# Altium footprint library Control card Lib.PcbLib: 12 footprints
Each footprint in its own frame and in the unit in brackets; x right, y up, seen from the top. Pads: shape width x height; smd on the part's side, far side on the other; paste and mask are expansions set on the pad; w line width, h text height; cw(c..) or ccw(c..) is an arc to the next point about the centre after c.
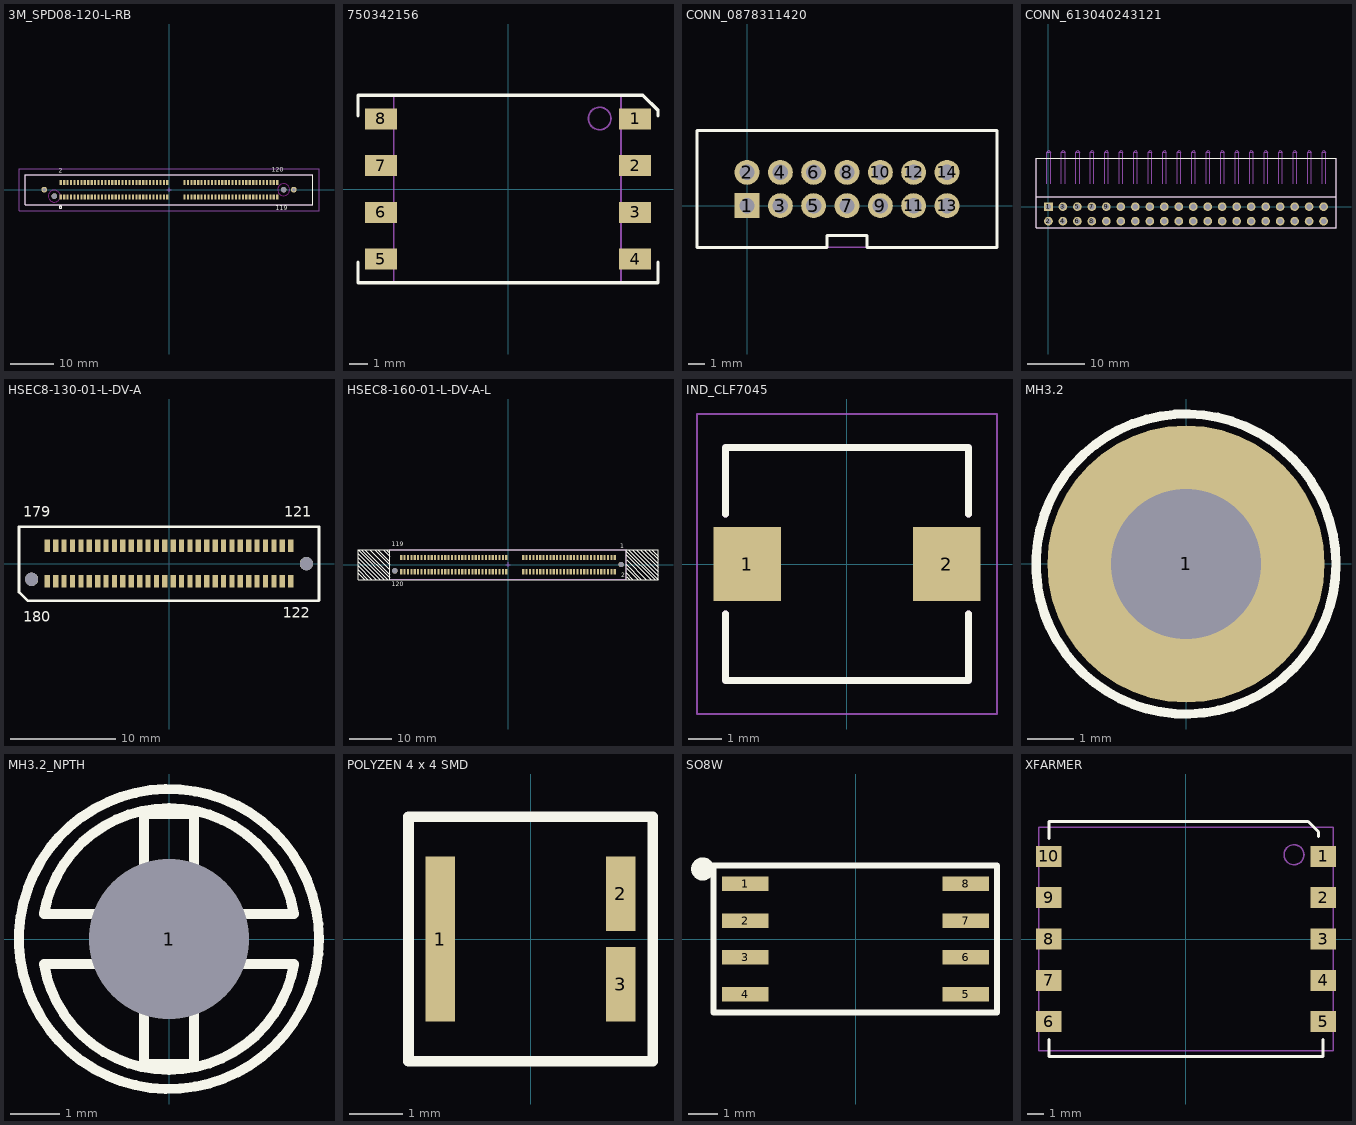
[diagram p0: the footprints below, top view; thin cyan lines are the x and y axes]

## 3M_SPD08-120-L-RB [mm] "CONN HIGH SPD CARD EDGE 120 POS"
height 12.4
pads (124):
  rect 0.5x1.2 smd mask+0: 1(-25.2,-1.7) 2(-25.2,1.7) 3(-24.4,-1.7) 4(-24.4,1.7) 5(-23.6,-1.7) 6(-23.6,1.7) 7(-22.8,-1.7) 8(-22.8,1.7) 9(-22,-1.7) 10(-22,1.7) 11(-21.2,-1.7) 12(-21.2,1.7) 13(-20.4,-1.7) 14(-20.4,1.7) 15(-19.6,-1.7) 16(-19.6,1.7) 17(-18.8,-1.7) 18(-18.8,1.7) 19(-18,-1.7) 20(-18,1.7) 21(-17.2,-1.7) 22(-17.2,1.7) 23(-16.4,-1.7) 24(-16.4,1.7) 25(-15.6,-1.7) 26(-15.6,1.7) 27(-14.8,-1.7) 28(-14.8,1.7) 29(-14,-1.7) 30(-14,1.7) 31(-13.2,-1.7) 32(-13.2,1.7) 33(-12.4,-1.7) 34(-12.4,1.7) 35(-11.6,-1.7) 36(-11.6,1.7) 37(-10.8,-1.7) 38(-10.8,1.7) 39(-10,-1.7) 40(-10,1.7) 41(-9.2,-1.7) 42(-9.2,1.7) 43(-8.4,-1.7) 44(-8.4,1.7) 45(-7.6,-1.7) 46(-7.6,1.7) 47(-6.8,-1.7) 48(-6.8,1.7) 49(-6,-1.7) 50(-6,1.7) 51(-5.2,-1.7) 52(-5.2,1.7) 53(-4.4,-1.7) 54(-4.4,1.7) 55(-3.6,-1.7) 56(-3.6,1.7) 57(-2.8,-1.7) 58(-2.8,1.7) 59(-2,-1.7) 60(-2,1.7) 61(-1.2,-1.7) 62(-1.2,1.7) 63(-0.4,-1.7) 64(-0.4,1.7) 65(3.6,-1.7) 66(3.6,1.7) 67(4.4,-1.7) 68(4.4,1.7) 69(5.2,-1.7) 70(5.2,1.7) 71(6,-1.7) 72(6,1.7) 73(6.8,-1.7) 74(6.8,1.7) 75(7.6,-1.7) 76(7.6,1.7) 77(8.4,-1.7) 78(8.4,1.7) 79(9.2,-1.7) 80(9.2,1.7) 81(10,-1.7) 82(10,1.7) 83(10.8,-1.7) 84(10.8,1.7) 85(11.6,-1.7) 86(11.6,1.7) 87(12.4,-1.7) 88(12.4,1.7) 89(13.2,-1.7) 90(13.2,1.7) 91(14,-1.7) 92(14,1.7) 93(14.8,-1.7) 94(14.8,1.7) 95(15.6,-1.7) 96(15.6,1.7) 97(16.4,-1.7) 98(16.4,1.7) 99(17.2,-1.7) 100(17.2,1.7) 101(18,-1.7) 102(18,1.7) 103(18.8,-1.7) 104(18.8,1.7) 105(19.6,-1.7) 106(19.6,1.7) 107(20.4,-1.7) 108(20.4,1.7) 109(21.2,-1.7) 110(21.2,1.7) 111(22,-1.7) 112(22,1.7) 113(22.8,-1.7) 114(22.8,1.7) 115(23.6,-1.7) 116(23.6,1.7) 117(24.4,-1.7) 118(24.4,1.7) 119(25.2,-1.7) 120(25.2,1.7)
  round 1.27 hole 1.27 unplated mask+0: 121(-26.7,-1.5) 122(26.7,0)
  round 1.34 hole 0.84 mask+0: 123(-29.05,0) 124(29.05,0)
Top Overlay:
  circle w0.152: c-25.279,-4.1 r0.279
  lines w0.152: 27.9,-3.556 27.9,-3.556 ; 27.9,3.5 27.9,3.5
  lines w0.178: -33.525,-3.5 -33.525,3.5 33.525,3.5 33.525,-3.5 -33.525,-3.5
  text "119" at 24.9,-4.8 h1.02
  text "2" at -25.7,3.9 h1.02
  text "120" at 23.9,4.2 h1.02
Keep-Out Layer:
  circle w0.152: c26.7,0 r1.397
  circle w0.152: c-26.7,-1.5 r1.397
Mechanical 5:
  lines w0.127: -33.525,-3.5 -33.525,3.5 33.525,3.5 33.525,-3.5 -33.525,-3.5
Mechanical 9:
  circle w0.025: c-25.279,-4.1 r0.279
  text ".Designator" at -6.096,-0.508 h1.27
Mechanical 15:
  lines w0.1: -0.5,0 0.5,0 ; 0,-0.5 0,0.5
  lines w0.127: -34.922,-4.897 -34.922,4.897 34.922,4.897 34.922,-4.897 -34.922,-4.897

## 750342156 [mm]
height 11.5
pads (8):
  rect 1.7x1.12 smd: 1(6.78,3.735) 2(6.78,1.245) 3(6.78,-1.245) 4(6.78,-3.735) 5(-6.78,-3.735) 6(-6.78,-1.245) 7(-6.78,1.245) 8(-6.78,3.735)
Top Overlay:
  lines w0.18: -8.001,-3.9 -8.001,-5 8.001,-5 8.001,-3.9 ; -8.001,3.9 -8.001,5 7.192,5 8.001,4.191 8.001,3.9
Mechanical 5:
  circle w0.1: c4.886,3.759 r0.6
  lines w0.1: -6.096,-5 6.035,-5 6.035,5 -6.096,5 -6.096,-5
  text ".Designator" at -2,-0.5 h1.02
3D body: height 5.97, standoff 0, extent -6.034,-4.999 6.034,4.999
3D body: height 5.98, standoff 5, extent 4.266,3.123 5.488,4.345

## CONN_0878311420 [mm]
height 6.35
pads (14):
  rect 1.5x1.5 hole 0.914: 1(0,0)
  round 1.5 hole 0.914: 2(0,2) 3(2,0) 4(2,2) 5(4,0) 6(4,2) 7(6,0) 8(6,2) 9(8,0) 10(8,2) 11(10,0) 12(10,2) 13(12,0) 14(12,2)
Top Overlay:
  lines w0.178: -3,-2.5 -3,4.5 15,4.5 15,-2.5 10.5,-2.5 7.2,-2.5 7.2,-1.8 4.8,-1.8 4.8,-2.5 -3,-2.5
Mechanical 5:
  lines w0.1: -3,-2.5 -3,4.5 15,4.5 15,-2.5 -3,-2.5
  text ".Designator" at 1.1,0.7 h1.02

## CONN_613040243121 [mil]
pads (40):
  rect 60x60 hole 38: 1(0,0)
  round 60 hole 38: 2(0,-100) 3(100,0) 4(100,-100) 5(200,0) 6(200,-100) 7(300,0) 8(300,-100) 9(400,0) 10(400,-100) 11(500,0) 12(500,-100) 13(600,0) 14(600,-100) 15(700,0) 16(700,-100) 17(800,0) 18(800,-100) 19(900,0) 20(900,-100) 21(1000,0) 22(1000,-100) 23(1100,0) 24(1100,-100) 25(1200,0) 26(1200,-100) 27(1300,0) 28(1300,-100) 29(1400,0) 30(1400,-100) 31(1500,0) 32(1500,-100) 33(1600,0) 34(1600,-100) 35(1700,0) 36(1700,-100) 37(1800,0) 38(1800,-100) 39(1900,0) 40(1900,-100)
Top Overlay:
  lines w5: -86,70 1986,70 ; -85,-145.5 -85,335 1986,335 1986,-145.5 -85,-145.5
Mechanical 5:
  lines w5: -86,70 1986,70 ; -85,-145.5 1986,-145.5 1986,335 -85,335 -85,-145.5
  text ".Designator" at 877,-70 h40
Mechanical 17:
  lines w1: -10.5,160 -10.5,377.5 ; 14.5,160 14.5,377.5 ; 89.5,160 89.5,377.5 ; 114.5,160 114.5,377.5 ; 189.5,160 189.5,377.5 ; 214.5,160 214.5,377.5 ; 289.5,160 289.5,377.5 ; 314.5,160 314.5,377.5 ; 389.5,160 389.5,377.5 ; 414.5,160 414.5,377.5 ; 489.5,160 489.5,377.5 ; 514.5,160 514.5,377.5 ; 589.5,160 589.5,377.5 ; 614.5,160 614.5,377.5 ; 689.5,160 689.5,377.5 ; 714.5,160 714.5,377.5 ; 789.5,160 789.5,377.5 ; 814.5,160 814.5,377.5 ; 889.5,160 889.5,377.5 ; 914.5,160 914.5,377.5 ; 989.5,160 989.5,377.5 ; 1014.5,160 1014.5,377.5 ; 1089.5,160 1089.5,377.5 ; 1114.5,160 1114.5,377.5 ; 1189.5,160 1189.5,377.5 ; 1214.5,160 1214.5,377.5 ; 1289.5,160 1289.5,377.5 ; 1314.5,160 1314.5,377.5 ; 1389.5,160 1389.5,377.5 ; 1414.5,160 1414.5,377.5 ; 1489.5,160 1489.5,377.5 ; 1514.5,160 1514.5,377.5 ; 1589.5,160 1589.5,377.5 ; 1614.5,160 1614.5,377.5 ; 1689.5,160 1689.5,377.5 ; 1714.5,160 1714.5,377.5 ; 1789.5,160 1789.5,377.5 ; 1814.5,160 1814.5,377.5 ; 1889.5,160 1889.5,377.5 ; 1914.5,160 1914.5,377.5 ; -10.5,377.5 2,390 14.5,377.5 ; -10.5,377.5 14.5,377.5 ; 89.5,377.5 114.5,377.5 ; 89.5,377.5 102,390 114.5,377.5 ; 189.5,377.5 202,390 214.5,377.5 ; 189.5,377.5 214.5,377.5 ; 289.5,377.5 302,390 314.5,377.5 ; 289.5,377.5 314.5,377.5 ; 389.5,377.5 402,390 414.5,377.5 ; 389.5,377.5 414.5,377.5 ; 489.5,377.5 514.5,377.5 ; 489.5,377.5 502,390 514.5,377.5 ; 589.5,377.5 602,390 614.5,377.5 ; 589.5,377.5 614.5,377.5 ; 689.5,377.5 702,390 714.5,377.5 ; 689.5,377.5 714.5,377.5 ; 789.5,377.5 802,390 814.5,377.5 ; 789.5,377.5 814.5,377.5 ; 889.5,377.5 902,390 914.5,377.5 ; 889.5,377.5 914.5,377.5 ; 989.5,377.5 1014.5,377.5 ; 989.5,377.5 1002,390 1014.5,377.5 ; 1089.5,377.5 1114.5,377.5 ; 1089.5,377.5 1102,390 1114.5,377.5 ; 1189.5,377.5 1214.5,377.5 ; 1189.5,377.5 1202,390 1214.5,377.5 ; 1289.5,377.5 1302,390 1314.5,377.5 ; 1289.5,377.5 1314.5,377.5 ; 1389.5,377.5 1402,390 1414.5,377.5 ; 1389.5,377.5 1414.5,377.5 ; 1489.5,377.5 1502,390 1514.5,377.5 ; 1489.5,377.5 1514.5,377.5 ; 1589.5,377.5 1602,390 1614.5,377.5 ; 1589.5,377.5 1614.5,377.5 ; 1689.5,377.5 1702,390 1714.5,377.5 ; 1689.5,377.5 1714.5,377.5 ; 1789.5,377.5 1802,390 1814.5,377.5 ; 1789.5,377.5 1814.5,377.5 ; 1889.5,377.5 1902,390 1914.5,377.5 ; 1889.5,377.5 1914.5,377.5

## HSEC8-130-01-L-DV-A [mm]
pads (62):
  rect 0.5x1.2 smd: 121(11.6,1.7) 122(11.6,-1.7) 123(10.8,1.7) 124(10.8,-1.7) 125(10,1.7) 126(10,-1.7) 127(9.2,1.7) 128(9.2,-1.7) 129(8.4,1.7) 130(8.4,-1.7) 131(7.6,1.7) 132(7.6,-1.7) 133(6.8,1.7) 134(6.8,-1.7) 135(6,1.7) 136(6,-1.7) 137(5.2,1.7) 138(5.2,-1.7) 139(4.4,1.7) 140(4.4,-1.7) 141(3.6,1.7) 142(3.6,-1.7) 143(2.8,1.7) 144(2.8,-1.7) 145(2,1.7) 146(2,-1.7) 147(1.2,1.7) 148(1.2,-1.7) 149(0.4,1.7) 150(0.4,-1.7) 151(-0.4,1.7) 152(-0.4,-1.7) 153(-1.2,1.7) 154(-1.2,-1.7) 155(-2,1.7) 156(-2,-1.7) 157(-2.8,1.7) 158(-2.8,-1.7) 159(-3.6,1.7) 160(-3.6,-1.7) 161(-4.4,1.7) 162(-4.4,-1.7) 163(-5.2,1.7) 164(-5.2,-1.7) 165(-6,1.7) 166(-6,-1.7) 167(-6.8,1.7) 168(-6.8,-1.7) 169(-7.6,1.7) 170(-7.6,-1.7) 171(-8.4,1.7) 172(-8.4,-1.7) 173(-9.2,1.7) 174(-9.2,-1.7) 175(-10,1.7) 176(-10,-1.7) 177(-10.8,1.7) 178(-10.8,-1.7) 179(-11.6,1.7) 180(-11.6,-1.7)
  round 1.27 hole 1.27 unplated mask+0: 181(13.1,0) 182(-13.1,-1.5)
Top Overlay:
  lines w0.254: 14.246,-3.554 -13.464,-3.554 -14.3,-2.718 -14.3,1.75 -14.3,3.5 14.3,3.5 14.3,-3.5
  text "180" at -13.898,-5.563 h1.02
  text "179" at -13.898,4.47 h1.02
  text "121" at 10.994,4.47 h1.02
  text "122" at 10.867,-5.182 h1.02
Mechanical 13:
  lines w0.1: -14.3,-2.7 -14.3,3.5 14.3,3.5 14.3,-3.5 -13.5,-3.5 -14.3,-2.7

## HSEC8-160-01-L-DV-A-L [mm]
pads (122):
  rect 0.5x1.2 smd: 1(25.2,1.7) 2(25.2,-1.7) 3(24.4,1.7) 4(24.4,-1.7) 5(23.6,1.7) 6(23.6,-1.7) 7(22.8,1.7) 8(22.8,-1.7) 9(22,1.7) 10(22,-1.7) 11(21.2,1.7) 12(21.2,-1.7) 13(20.4,1.7) 14(20.4,-1.7) 15(19.6,1.7) 16(19.6,-1.7) 17(18.8,1.7) 18(18.8,-1.7) 19(18,1.7) 20(18,-1.7) 21(17.2,1.7) 22(17.2,-1.7) 23(16.4,1.7) 24(16.4,-1.7) 25(15.6,1.7) 26(15.6,-1.7) 27(14.8,1.7) 28(14.8,-1.7) 29(14,1.7) 30(14,-1.7) 31(13.2,1.7) 32(13.2,-1.7) 33(12.4,1.7) 34(12.4,-1.7) 35(11.6,1.7) 36(11.6,-1.7) 37(10.8,1.7) 38(10.8,-1.7) 39(10,1.7) 40(10,-1.7) 41(9.2,1.7) 42(9.2,-1.7) 43(8.4,1.7) 44(8.4,-1.7) 45(7.6,1.7) 46(7.6,-1.7) 47(6.8,1.7) 48(6.8,-1.7) 49(6,1.7) 50(6,-1.7) 51(5.2,1.7) 52(5.2,-1.7) 53(4.4,1.7) 54(4.4,-1.7) 55(3.6,1.7) 56(3.6,-1.7) 57(-0.4,1.7) 58(-0.4,-1.7) 59(-1.2,1.7) 60(-1.2,-1.7) 61(-2,1.7) 62(-2,-1.7) 63(-2.8,1.7) 64(-2.8,-1.7) 65(-3.6,1.7) 66(-3.6,-1.7) 67(-4.4,1.7) 68(-4.4,-1.7) 69(-5.2,1.7) 70(-5.2,-1.7) 71(-6,1.7) 72(-6,-1.7) 73(-6.8,1.7) 74(-6.8,-1.7) 75(-7.6,1.7) 76(-7.6,-1.7) 77(-8.4,1.7) 78(-8.4,-1.7) 79(-9.2,1.7) 80(-9.2,-1.7) 81(-10,1.7) 82(-10,-1.7) 83(-10.8,1.7) 84(-10.8,-1.7) 85(-11.6,1.7) 86(-11.6,-1.7) 87(-12.4,1.7) 88(-12.4,-1.7) 89(-13.2,1.7) 90(-13.2,-1.7) 91(-14,1.7) 92(-14,-1.7) 93(-14.8,1.7) 94(-14.8,-1.7) 95(-15.6,1.7) 96(-15.6,-1.7) 97(-16.4,1.7) 98(-16.4,-1.7) 99(-17.2,1.7) 100(-17.2,-1.7) 101(-18,1.7) 102(-18,-1.7) 103(-18.8,1.7) 104(-18.8,-1.7) 105(-19.6,1.7) 106(-19.6,-1.7) 107(-20.4,1.7) 108(-20.4,-1.7) 109(-21.2,1.7) 110(-21.2,-1.7) 111(-22,1.7) 112(-22,-1.7) 113(-22.8,1.7) 114(-22.8,-1.7) 115(-23.6,1.7) 116(-23.6,-1.7) 117(-24.4,1.7) 118(-24.4,-1.7) 119(-25.2,1.7) 120(-25.2,-1.7)
  round 1.27 hole 1.27 unplated mask+0: 121(-26.7,-1.5) 122(26.7,0)
Top Overlay:
  lines w0.2: -35.4,-2.032 -33.909,-3.523 ; -35.4,-1.27 -33.114,-3.556 ; -35.4,0.635 -31.242,-3.523 ; -35.4,1.651 -30.226,-3.523 ; -35.4,2.54 -29.337,-3.523 ; -35.353,-0.334 -32.131,-3.556 ; -34.58,3.465 -27.94,-3.175 ; -33.782,3.5 -27.9,-2.382 ; -32.639,3.5 -27.996,-1.143 ; -31.496,3.5 -27.9,-0.096 ; -30.734,3.5 -27.996,0.762 ; -29.464,3.5 -27.9,1.936 ; -28.702,3.5 -27.996,2.794 ; -28.344,-3.556 -35.4,3.5 ; 27.9,-1.992 29.464,-3.556 ; 27.9,0.04 31.496,-3.556 ; 27.9,2.326 33.782,-3.556 ; 27.94,3.119 34.58,-3.52 ; 27.996,-2.85 28.702,-3.556 ; 27.996,-0.818 30.734,-3.556 ; 27.996,1.087 32.639,-3.556 ; 28.344,3.5 35.4,-3.556 ; 29.337,3.467 35.4,-2.596 ; 30.226,3.467 35.4,-1.707 ; 31.242,3.467 35.4,-0.691 ; 32.131,3.5 35.353,0.278 ; 33.114,3.5 35.4,1.214 ; 33.909,3.467 35.4,1.976 ; -35.4,3.5 -27.9,3.5 ; -35.4,3.5 -35.4,-3.556 -27.9,-3.556 ; -27.9,-3.556 -27.9,3.5 ; -27.9,-3.556 27.9,-3.556 ; -27.9,3.5 27.9,3.5 ; 27.9,-3.556 27.9,3.5 ; 27.9,-3.556 35.4,-3.556 ; 27.9,-3.556 27.9,3.5 ; 27.9,3.5 35.4,3.5 35.4,-3.556
  text "2" at 26.67,-3.048 h1.02
  text "1" at 26.543,3.81 h1.02
  text "119" at -27.432,4.318 h1.02
  text "120" at -27.432,-5.08 h1.02
Mechanical 13:
  lines w0.1: 27.9,-3.556 27.9,3.444 ; -27.9,-3.5 27.9,-3.5 27.9,3.5 -27.9,3.5 -27.9,-3.5
Mechanical 15:
  lines w0.1: -0.5,0 0.5,0 ; 0,-0.5 0,0.5

## IND_CLF7045 [mm]
height 4.5
pads (2):
  rect 2x2.2 smd: 1(-2.95,0) 2(2.95,0)
Top Overlay:
  lines w0.2: -3.6,-1.473 -3.6,-3.45 3.6,-3.45 3.6,-1.473 ; -3.6,1.473 -3.6,3.45 3.6,3.45 3.6,1.473
Mechanical 5:
  lines w0.2: -3.6,-1.473 -3.6,-3.45 3.6,-3.45 3.6,-1.473 ; -3.6,1.473 -3.6,3.45 3.6,3.45 3.6,1.473
Mechanical 15:
  lines w0.051: -4.445,-4.445 4.445,-4.445 4.445,4.445 -4.445,4.445 -4.445,-4.445
3D body: height 4.5, standoff 0, extent -3.6,-3.45 3.6,3.45

## MH3.2 [mm]
pads (1):
  round 6 / inner round 3.607 / far side round 6 hole 3.251: 1(0,0)
Top Overlay:
  lines w0.203: 3.25,0 cw(c0,0) 3.25,0.014

## MH3.2_NPTH [mil]
pads (1):
  round 20 / inner round 142 / far side round 20 hole 128 unplated: 1(0,0)
Top Overlay:
  circle w8: c0,0 r120
  lines w8: -100,-20 -20,-20 -20,-100 20,-100 20,-20 100,-20 ; -100.02,-19.91 ccw(c0,-3.35) 99.99,-20.08 ; -100,20 -20,20 -20,100 20,100 20,20 100,20 ; -99.99,20.09 cw(c0,3.36) 100.02,19.92

## POLYZEN 4 x 4 SMD [mm]
height 2
pads (3):
  rect 0.56x3.1 smd: 1(-1.7,0)
  rect 0.56x1.4 smd: 2(1.7,0.85) 3(1.7,-0.85)
Top Overlay:
  lines w0.2: -2.3,-2.3 2.3,-2.3 2.3,2.3 -2.3,2.3 -2.3,-2.3

## SO8W [mm]
height 2.5
pads (8):
  rect 1.6x0.5 smd: 1(-3.81,1.905) 2(-3.81,0.635) 3(-3.81,-0.635) 4(-3.81,-1.905) 5(3.81,-1.905) 6(3.81,-0.635) 7(3.81,0.635) 8(3.81,1.905)
Top Overlay:
  circle w0.4: c-5.28,2.421 r0.2
  lines w0.2: -4.91,-2.54 -4.91,2.54 4.89,2.54 4.89,-2.54 -4.91,-2.54

## XFARMER [mil]
height 500
pads (10):
  rect 61x50 smd: 1(325.5,196) 2(325.5,98) 3(325.5,0) 4(325.5,-98) 5(325.5,-196) 6(-325.5,-196) 7(-325.5,-98) 8(-325.5,0) 9(-325.5,98) 10(-325.5,196)
Top Overlay:
  lines w7.09: -325.5,-239 -325.5,-279 325.5,-279 325.5,-239 ; -325.5,239 -325.5,279 290,279 314.5,254.5 314.5,243.04
Mechanical 5:
  circle w3.94: c256.38,200 r23.62
  lines w4: -349.5,-265 -349.5,265 349.5,265 349.5,-265 -349.5,-265
  text ".Designator" at -200,-10 h40
3D body: height 177.17, standoff 0, extent -349.5,-265 349.5,265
